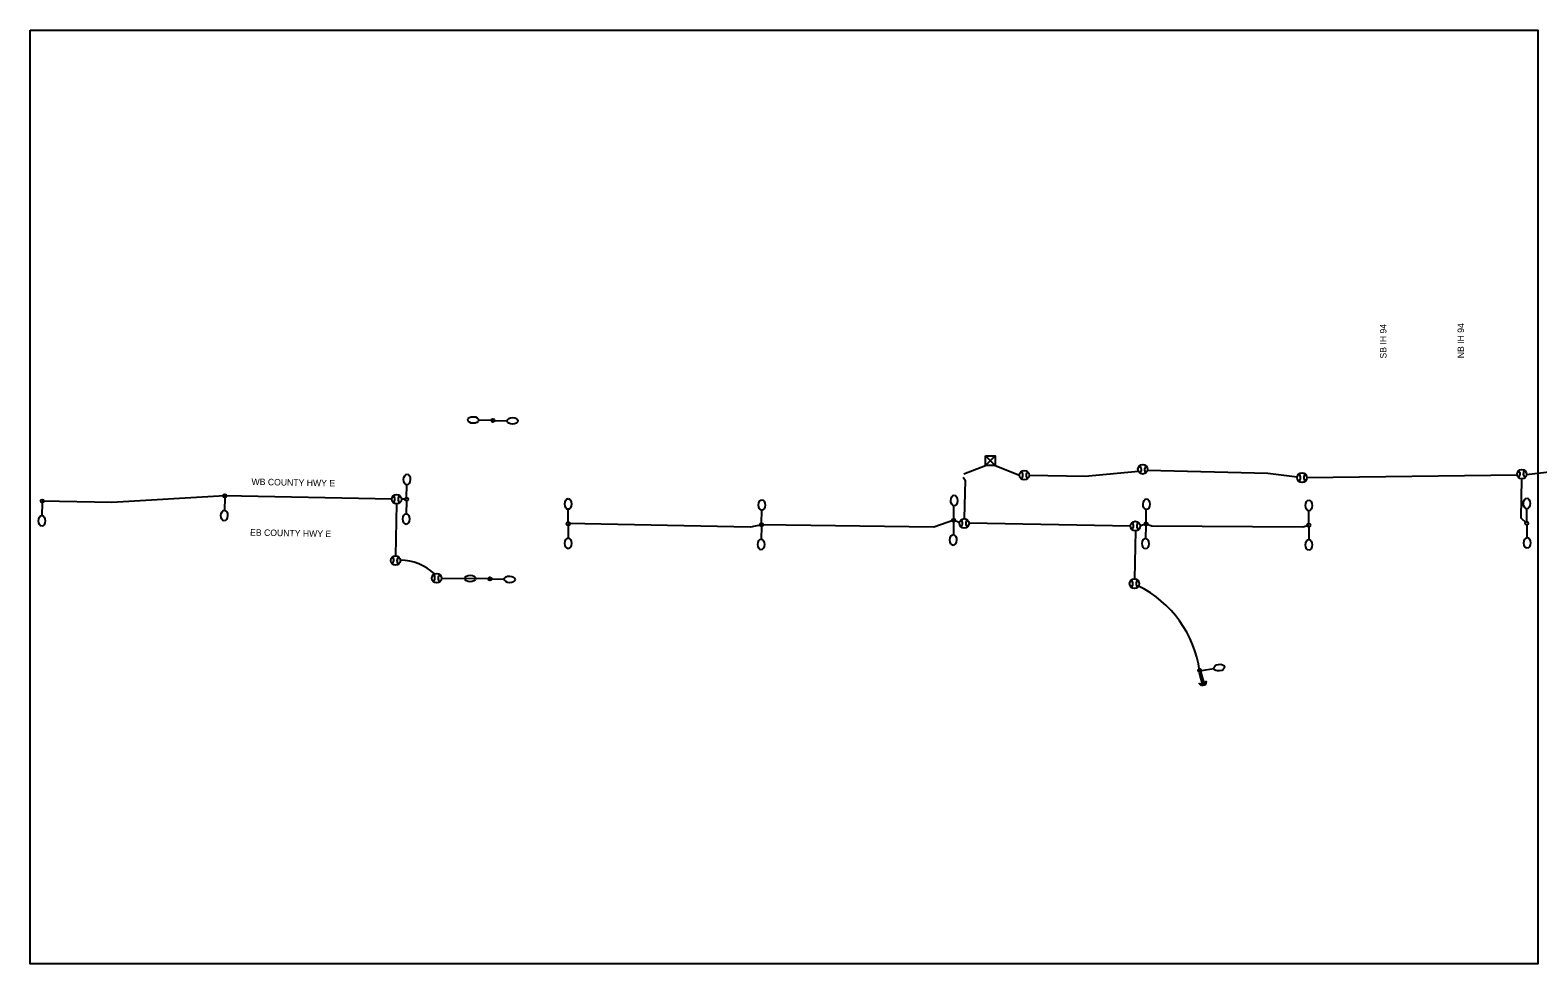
# Model space of a CAD drawing. Extents: x 589059 to 596052, y 152647 to 154942.
# Drawn here: x 592902 to 594477, y 153967 to 154942 of the extents above; entities that cross this region are included whole.
import ezdxf

# ---------------------------------------------------------------- set-up
doc = ezdxf.new("R2010")
doc.units = 0
doc.layers.add('Level 26', color=7, linetype='Continuous')
doc.layers.add('P_DRN_Flow', color=7, linetype='Continuous')

msp = doc.modelspace()

# ---------------------------------------------------------------- linework, layer by layer
at = {"layer": 'Level 26'}
for p, q in [((593385, 154534.5), (593370, 154534.8)), ((593385, 154534.5), (593400, 154534.2)), ((593876.9, 154478.8), (593899.6, 154487.4)), ((593899.6, 154487.4), (593909.6, 154497.4)), ((593899.6, 154497.4), (593909.6, 154487.4)), ((593909.6, 154487.4), (593935.1, 154477.3)), ((594235.3, 154474.7), (594454.9, 154477.6)), ((594464.9, 154478.1), (594497.2, 154481.7)), ((593104.8, 154453.9), (593104.5, 154440.7)), ((593294.8, 154453.8), (593295, 154467.1)), ((592914.2, 154448.4), (592913.9, 154435.2)), ((593284.3, 154447.2), (593283.4, 154393.2)), ((593294.7, 154450.3), (593294.5, 154437.1)), ((593463.7, 154428.5), (593463.6, 154441.7)), ((593463.7, 154428.2), (593463.7, 154441.5)), ((593665.6, 154427.3), (593665.9, 154440.5)), ((593866.4, 154432), (593866.7, 154445.2)), ((594067.3, 154428.2), (594067.6, 154441.4)), ((594237.3, 154426.9), (594237.3, 154440.1)), ((594465, 154428.8), (594465, 154442.1)), ((593463.7, 154425), (593463.7, 154411.7)), ((593665.6, 154423.8), (593665.3, 154410.5)), ((593866.3, 154428.5), (593866.1, 154415.2)), ((594061.1, 154424.6), (594067.3, 154426.5)), ((594067.2, 154424.7), (594066.9, 154411.4)), ((594067.3, 154426.5), (594073.4, 154424.4)), ((594073.4, 154424.4), (594231.1, 154423.3)), ((594231.1, 154423.3), (594237.3, 154425.1)), ((594237.3, 154423.4), (594237.3, 154410.1)), ((594465, 154425.3), (594465.3, 154412.1)), ((594056.2, 154419.1), (594055.3, 154369.1)), ((593381.9, 154369), (593331.3, 154369.5)), ((593381.9, 154369), (593366.9, 154369.3)), ((593381.9, 154369), (593396.9, 154368.6)), ((594125.1, 154273.4), (594138.2, 154275.5))]:
    msp.add_line(p, q, dxfattribs=at)
for points in [[(593899.6, 154497.4), (593909.6, 154497.4), (593909.6, 154487.4), (593899.6, 154487.4)], [(594125.4, 154257.3), (594122.9, 154259.8), (594126.9, 154259.5), (594130.2, 154261.7), (594129.3, 154258.3)]]:
    msp.add_lwpolyline(points, close=True, dxfattribs=at)
for points in [[(593876.4, 154475.2), (593878.3, 154472), (593877.4, 154431.9)], [(593945.1, 154477.3), (594003.9, 154476.3), (594059.3, 154481.5)], [(594068.8, 154482.4), (594194.4, 154479.4), (594225.3, 154475.6)], [(594464.9, 154427.3), (594459.3, 154432.5), (594459.9, 154473.3)], [(593279.4, 154452.4), (593104.8, 154455.7), (592987, 154448.7), (592914.2, 154450.2)], [(593294.8, 154452.3), (593289.4, 154452.4)], [(593872.5, 154427.5), (593866.4, 154430.2), (593845.5, 154423.1), (593665.5, 154425.5), (593654, 154423.1), (593463.7, 154426.7)], [(594051.1, 154424.1), (594051.1, 154424.1), (593882.4, 154427.2)], [(594122.8, 154270.9), (594126.4, 154257.6)], [(594124.7, 154271.4), (594128.3, 154258.1)]]:
    msp.add_lwpolyline(points, dxfattribs=at)
for centre, radius in [((593385, 154534.5), 1.76), ((594063.9, 154483.5), 5), ((594459.9, 154478.3), 5), ((593940.1, 154477.3), 5), ((594230.3, 154474.7), 5), ((592914.2, 154450.2), 1.76), ((593104.8, 154455.7), 1.76), ((593284.4, 154452.2), 5), ((593294.8, 154452.1), 1.76), ((593463.7, 154426.7), 1.76), ((593463.7, 154426.5), 1.76), ((593665.6, 154425.5), 1.76), ((593665.6, 154425.5), 1.76), ((593866.4, 154430.2), 1.76), ((593866.4, 154430.2), 1.76), ((593877.4, 154426.9), 5), ((594056.1, 154424.1), 5), ((594067.2, 154426.4), 1.76), ((594067.2, 154426.4), 1.76), ((594237.3, 154425.1), 1.76), ((594237.3, 154425.1), 1.76), ((594465, 154427.1), 1.76), ((594465, 154427.1), 1.76), ((593283.3, 154388.2), 5), ((593326.3, 154369.7), 5), ((593381.9, 154369), 1.76), ((594055.2, 154364), 5), ((594123.4, 154273.2), 1.76)]:
    msp.add_circle(centre, radius, dxfattribs=at)
for centre, radius, start, end in [((594057.5, 154483.2), 5, 312.3956, 51.6258), ((594070.8, 154483.3), 5, 131.5526, 225.5816), ((593933.7, 154477.1), 5, 312.3956, 51.6258), ((593947, 154477.2), 5, 131.5526, 225.5816), ((594223.8, 154474.5), 5, 312.3956, 51.6258), ((594237.1, 154474.6), 5, 131.5526, 225.5816), ((594453.1, 154478.5), 5, 311.5526, 45.5816), ((594466.4, 154478.6), 5, 132.3956, 231.6258), ((593277.6, 154452.6), 5, 309.3835, 43.4125), ((593290.9, 154452.2), 5, 130.2265, 229.4568), ((593870.6, 154427.3), 5, 309.3835, 43.4125), ((593883.9, 154426.9), 5, 130.2265, 229.4568), ((594049.3, 154424.6), 5, 309.3835, 43.4125), ((594062.6, 154424.1), 5, 130.2265, 229.4568), ((593276.4, 154388.6), 5, 309.3835, 43.4125), ((593289.7, 154388.2), 5, 130.2265, 229.4568), ((593287.6, 154335.6), 53, 46.6417, 89.2762), ((593319.5, 154370.1), 5, 309.3835, 43.4125), ((593332.8, 154369.6), 5, 130.2265, 229.4568), ((594048.7, 154363.8), 5, 312.3956, 51.6258), ((594062, 154363.8), 5, 131.5526, 225.5816), ((594007.4, 154256.8), 117, 8.0245, 63.5427)]:
    msp.add_arc(centre, radius, start, end, dxfattribs=at)
for centre, major_axis in [((593364.4, 154534.9), (-5.59, 0.12)), ((593405.6, 154534), (5.59, -0.12)), ((593295.2, 154472.7), (0.11, 5.59)), ((593463.6, 154447.3), (-0.02, 5.6)), ((593463.7, 154447.1), (0, 5.6)), ((593666, 154446.1), (0.11, 5.59)), ((593866.8, 154450.8), (0.11, 5.59)), ((594067.7, 154447), (0.11, 5.59)), ((594465, 154447.7), (0, 5.6)), ((593104.4, 154435.1), (-0.11, -5.59)), ((593294.4, 154431.5), (-0.11, -5.59)), ((594237.3, 154445.7), (0, 5.6)), ((592913.8, 154429.6), (-0.11, -5.59)), ((593463.7, 154406.1), (0.02, -5.6)), ((593665.2, 154404.9), (-0.11, -5.59)), ((593865.9, 154409.6), (-0.11, -5.59)), ((594066.8, 154405.8), (-0.11, -5.59)), ((594237.3, 154404.5), (0, -5.6)), ((594465.5, 154406.5), (0.14, -5.59)), ((593361.3, 154369.4), (-5.59, 0.12)), ((593402.5, 154368.5), (5.59, -0.12)), ((594143.7, 154276.3), (5.53, 0.86))]:
    msp.add_ellipse(centre, major_axis=major_axis, ratio=0.621156, dxfattribs=at)
at = {"layer": 'P_DRN_Flow'}
msp.add_lwpolyline([(592901.6, 154942), (594476.6, 154942), (594476.6, 153967), (592901.6, 153967)], close=True, dxfattribs=at)

# ---------------------------------------------------------------- texts
for s, rotation, p in [('SB IH 94', 90.0238, (594318.5, 154599.1)), ('NB IH 94', 90.0238, (594399.5, 154599.4)), ('WB COUNTY HWY E', 358.9238, (593132.8, 154467.1)), ('EB COUNTY HWY E', 358.9238, (593131.3, 154414.2))]:
    msp.add_text(s, height=6.75, rotation=rotation, dxfattribs=at).set_placement(p)

doc.saveas('drawing.dxf')
